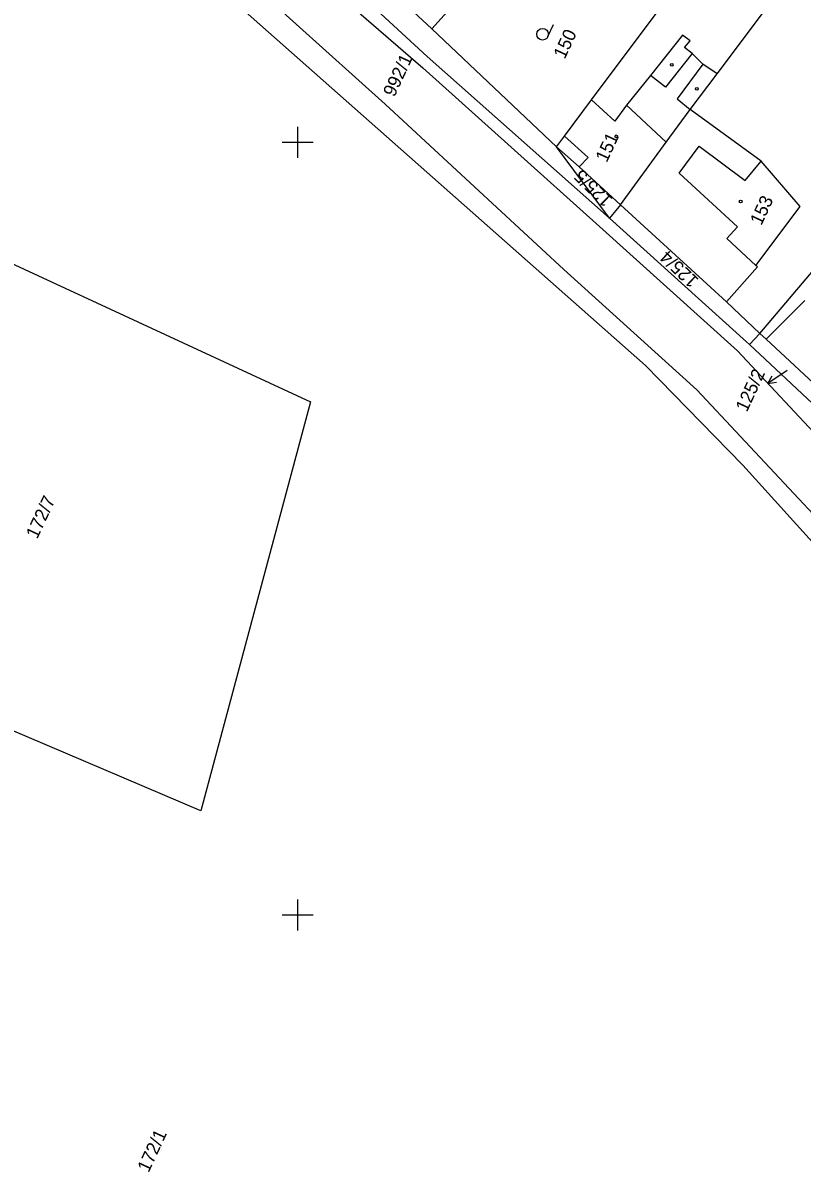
# Model space of a CAD drawing. Extents: x -755344 to -754412, y -1162670 to -1161477.
# Drawn here: x -754935.5 to -754834.8, y -1161933.3 to -1161784.6 of the extents above; entities that cross this region are included whole.
import ezdxf

# ---------------------------------------------------------------- set-up
doc = ezdxf.new("R2010")
doc.units = 0
for name, color, linetype in [('Síť', 7, 'Continuous'), ('Vrstva 55', 7, 'Continuous'), ('Vrstva 56', 7, 'Continuous'), ('Vrstva 57', 7, 'Continuous'), ('Vrstva 58', 7, 'Continuous'), ('Vrstva 59', 7, 'Continuous')]:
    doc.layers.add(name, color=color, linetype=linetype)

msp = doc.modelspace()

# ---------------------------------------------------------------- linework, layer by layer
at = {"layer": 'Síť'}
for points in [[(-754900, -1161798), (-754900, -1161800), (-754900, -1161802)], [(-754898, -1161800), (-754900, -1161800), (-754902, -1161800)], [(-754900, -1161898), (-754900, -1161900), (-754900, -1161902)], [(-754898, -1161900), (-754900, -1161900), (-754902, -1161900)]]:
    msp.add_lwpolyline(points, dxfattribs=at)
at = {"layer": 'Vrstva 55'}
for p, q in [((-754861.99, -1161794.51), (-754846.5, -1161773.77)), ((-754845.76, -1161791.14), (-754833.48, -1161774.78)), ((-754885, -1161783.11), (-754882.65, -1161785.33)), ((-754882.65, -1161785.33), (-754866.5, -1161800.56)), ((-754849.21, -1161795.73), (-754845.76, -1161791.14)), ((-754859.67, -1161809.81), (-754866.5, -1161800.56)), ((-754858.25, -1161808.07), (-754859.67, -1161809.81)), ((-754858.25, -1161808.07), (-754844.55, -1161820.66)), ((-754844.55, -1161820.66), (-754840.24, -1161824.73)), ((-754840.24, -1161824.73), (-754841.56, -1161826.18)), ((-754841.56, -1161826.18), (-754832.73, -1161834.46))]:
    msp.add_line(p, q, dxfattribs=at)
for points in [[(-754992.13, -1161692.36), (-754991.87, -1161692.75), (-754961.05, -1161719.56), (-754924.16, -1161751.14), (-754883.24, -1161788.9), (-754859.67, -1161809.81)], [(-754790.69, -1161920.17), (-754823.33, -1161865.1), (-754831.37, -1161854.01), (-754842.43, -1161841.79), (-754855.01, -1161828.87), (-754953.69, -1161741.58)], [(-754882.65, -1161785.33), (-754871.6, -1161773.02), (-754864.38, -1161779.75), (-754855.38, -1161770.09), (-754853.46, -1161767.96), (-754850.61, -1161770.4), (-754846.5, -1161773.77)], [(-754845.76, -1161791.14), (-754847.59, -1161789.9), (-754848.96, -1161788.52), (-754849.95, -1161787.73), (-754849.24, -1161786.86), (-754850.23, -1161786.13), (-754854.38, -1161791.33), (-754857.45, -1161795.19), (-754858.98, -1161797.27), (-754861.99, -1161794.51)], [(-754866.5, -1161800.56), (-754865.48, -1161799.19), (-754861.99, -1161794.51)], [(-754858.25, -1161808.07), (-754852.33, -1161799.99), (-754849.21, -1161795.73)], [(-754844.55, -1161820.66), (-754840.54, -1161816.09), (-754840.72, -1161815.93), (-754835.01, -1161808.29), (-754840.05, -1161802.42), (-754849.21, -1161795.73)], [(-754866.5, -1161800.56), (-754863.59, -1161803.15), (-754858.25, -1161808.07)], [(-754957.73, -1161806.07), (-754898.34, -1161833.59), (-754912.51, -1161886.53), (-754987.52, -1161854.57), (-755005.46, -1161846.93), (-755029.96, -1161837.42)], [(-754859.67, -1161809.81), (-754841.94, -1161825.83), (-754841.56, -1161826.18)], [(-754840.24, -1161824.73), (-754832.54, -1161815.66), (-754829.3, -1161811.83)], [(-754840.24, -1161824.73), (-754839.41, -1161825.46), (-754831.41, -1161832.91)]]:
    msp.add_lwpolyline(points, dxfattribs=at)
at = {"layer": 'Vrstva 56'}
for p, q in [((-754926.26, -1161753.63), (-754883.79, -1161790.36)), ((-754888.68, -1161795.04), (-754908.58, -1161777.13)), ((-754848.96, -1161788.52), (-754852.42, -1161792.85)), ((-754847.59, -1161789.9), (-754850.91, -1161794.38)), ((-754883.79, -1161790.36), (-754860.97, -1161810.87)), ((-754852.42, -1161792.85), (-754854.38, -1161791.33)), ((-754850.91, -1161794.38), (-754849.21, -1161795.73)), ((-754865.57, -1161816.45), (-754888.68, -1161795.04)), ((-754857.45, -1161795.19), (-754852.33, -1161799.99)), ((-754865.48, -1161799.19), (-754862.43, -1161801.96)), ((-754850.66, -1161803.98), (-754848.05, -1161800.48)), ((-754848.05, -1161800.48), (-754842.11, -1161804.93)), ((-754862.43, -1161801.96), (-754863.59, -1161803.15)), ((-754842.11, -1161804.93), (-754840.05, -1161802.42)), ((-754843.11, -1161810.92), (-754850.66, -1161803.98)), ((-754843.11, -1161827), (-754860.97, -1161810.87)), ((-754844.49, -1161812.46), (-754843.11, -1161810.92)), ((-754840.72, -1161815.93), (-754844.49, -1161812.46)), ((-754865.57, -1161816.45), (-754848.39, -1161832.02)), ((-754834.41, -1161820.45), (-754839.41, -1161825.46)), ((-754825.18, -1161846.21), (-754843.11, -1161827)), ((-754848.39, -1161832.02), (-754831.41, -1161850.21))]:
    msp.add_line(p, q, dxfattribs=at)
at = {"layer": 'Vrstva 57'}
for p, q in [((-754836.68, -1161829.53), (-754839.17, -1161831.19)), ((-754839.17, -1161831.19), (-754838.62, -1161830.22)), ((-754839.17, -1161831.19), (-754838.06, -1161831.05))]:
    msp.add_line(p, q, dxfattribs=at)
at = {"layer": 'Vrstva 58'}
msp.add_line((-754867.64, -1161786.32), (-754866.9, -1161784.74), dxfattribs=at)
msp.add_circle((-754868.32, -1161786.01), 0.75, dxfattribs=at)
at = {"layer": 'Vrstva 59'}
for centre in [(-754851.62, -1161789.96), (-754848.37, -1161793.06), (-754858.78, -1161799.22), (-754842.7, -1161807.64)]:
    msp.add_circle(centre, 0.175, dxfattribs=at)

# ---------------------------------------------------------------- texts
at = {"layer": 'Vrstva 57'}
for s, rotation, p in [('150', 65, (-754865.46, -1161789.32)), ('992/1', 65, (-754887.49, -1161794.23)), ('151', 65, (-754860.02, -1161802.69)), ('125/5', 135.6551, (-754859.15, -1161807.34)), ('153', 65, (-754840.03, -1161810.85)), ('125/4', 136.4164, (-754848.02, -1161817.76)), ('125/2', 65, (-754841.9, -1161835)), ('172/7', 65, (-754933.68, -1161851.42)), ('172/1', 65, (-754919.27, -1161933.42))]:
    msp.add_text(s, height=1.7, rotation=rotation, dxfattribs=at).set_placement(p)

doc.saveas('drawing.dxf')
